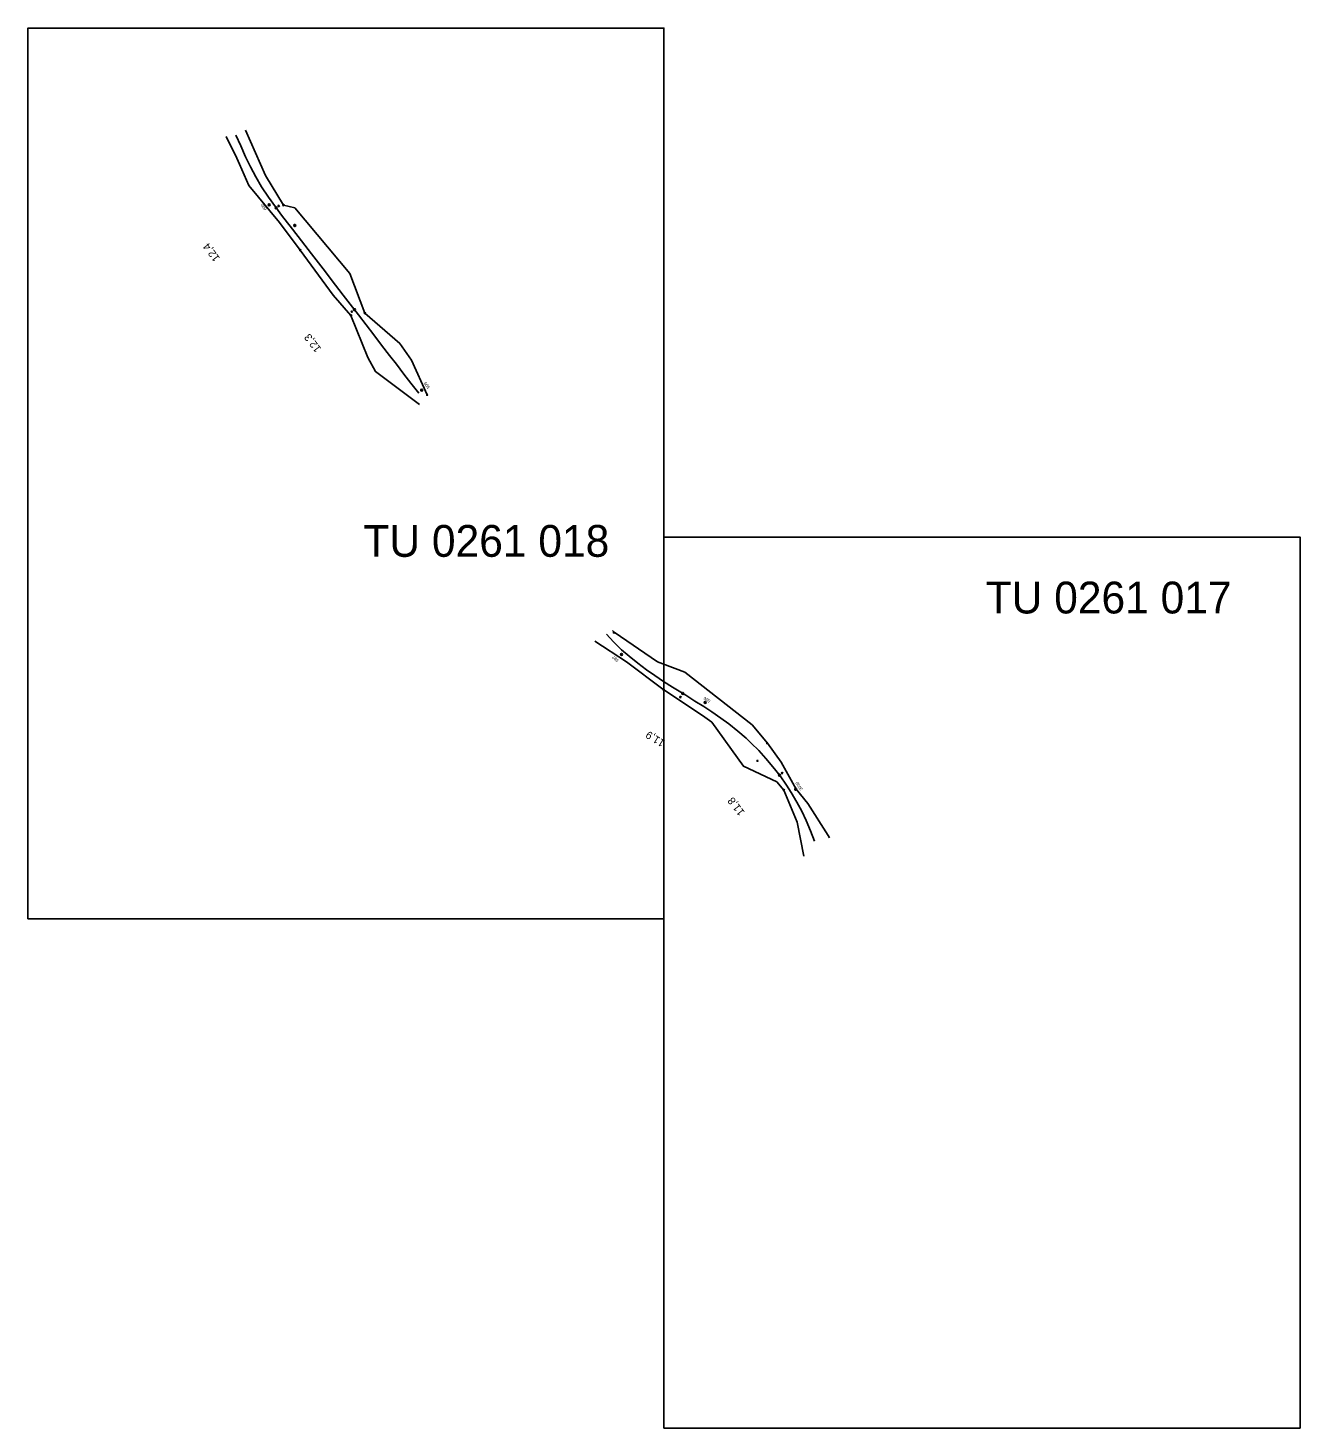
# Model space of a CAD drawing. Extents: x -849500 to -843400, y -1061500 to -1052696.
# Drawn here: x -849200 to -848200, y -1057300 to -1056200 of the extents above; entities that cross this region are included whole.
import ezdxf

# ---------------------------------------------------------------- set-up
doc = ezdxf.new("R2010")
doc.units = 0
for name, color, linetype in [('Level 1', 7, 'Continuous'), ('Level 2', 7, 'Continuous'), ('Vrstva 1', 7, 'Continuous'), ('Vrstva 53', 7, 'Continuous'), ('Vrstva 63', 7, 'Continuous'), ('Vrstva 7', 7, 'Continuous')]:
    doc.layers.add(name, color=color, linetype=linetype)

msp = doc.modelspace()

# ---------------------------------------------------------------- linework, layer by layer
at = {"layer": 'Level 1'}
for points in [[(-849200, -1056900), (-849200, -1056200), (-848700, -1056200), (-848700, -1056900), (-849200, -1056900)], [(-848700, -1057300), (-848700, -1056600), (-848200, -1056600), (-848200, -1057300), (-848700, -1057300)]]:
    msp.add_lwpolyline(points, dxfattribs=at)
at = {"layer": 'Vrstva 1'}
for points in [[(-848999.8, -1056348.1), (-849005.4, -1056340.6), (-849011, -1056332.8), (-849016.3, -1056324.7), (-849020.8, -1056317), (-849025, -1056309.1), (-849028.9, -1056301.1), (-849032.8, -1056292.6), (-849036.6, -1056284.2)], [(-848892.8, -1056486.9), (-848899, -1056479), (-848904.4, -1056471.9), (-848910.4, -1056464.2), (-848915.7, -1056457.3), (-848922, -1056449.1), (-848928.2, -1056441), (-848934.2, -1056433.2), (-848940.2, -1056425.4), (-848946.7, -1056417), (-848952.2, -1056409.8), (-848955.6, -1056405.5), (-848960.8, -1056398.7), (-848966.2, -1056391.7), (-848971.6, -1056384.6), (-848977.2, -1056377.4), (-848982.3, -1056370.7), (-848987.7, -1056363.8), (-848993.8, -1056355.8), (-848999.8, -1056348.1)], [(-848581.6, -1056838.8), (-848584.7, -1056830.7), (-848588.2, -1056822.7), (-848591.7, -1056815.3), (-848595.5, -1056808.2), (-848599.9, -1056800.8), (-848603.8, -1056794.8), (-848608.8, -1056787.6), (-848614.4, -1056780.4), (-848619.9, -1056773.9), (-848625.5, -1056767.8), (-848631.4, -1056761.9), (-848635.5, -1056758.1), (-848642, -1056752.5), (-848649.1, -1056746.8), (-848655.3, -1056742.3), (-848662.5, -1056737.4), (-848668.7, -1056733.2), (-848675.7, -1056728.8), (-848682.9, -1056724.3), (-848689.4, -1056720.3), (-848693.4, -1056717.8), (-848700.3, -1056713.4), (-848707.3, -1056708.8), (-848713.7, -1056704.3), (-848720.7, -1056699.1), (-848727.5, -1056693.6), (-848733.3, -1056688.5), (-848739.6, -1056682.4), (-848745.3, -1056676.4)]]:
    msp.add_lwpolyline(points, dxfattribs=at)
at = {"layer": 'Vrstva 53'}
for p, q in [((-848999.2, -1056339.1), (-848999.1, -1056339.1)), ((-848986.1, -1056374.5), (-848986, -1056374.5)), ((-848946.1, -1056425.8), (-848946, -1056425.8)), ((-848935.3, -1056424), (-848935.2, -1056424)), ((-848886.3, -1056488.2), (-848886.2, -1056488.2)), ((-848739.4, -1056675), (-848739.3, -1056675)), ((-848700.4, -1056719.9), (-848700.3, -1056719.9)), ((-848618.9, -1056761.9), (-848618.8, -1056761.9)), ((-848626.6, -1056775.8), (-848626.5, -1056775.8)), ((-848605.9, -1056798.8), (-848605.8, -1056798.8)), ((-848596.5, -1056798.1), (-848596.4, -1056798.1))]:
    msp.add_line(p, q, dxfattribs=at)
for points in [[(-849026.3, -1056323.7), (-849033.6, -1056307.1), (-849035.7, -1056302.4), (-849044.2, -1056285.3)], [(-849029, -1056280.3), (-849013.3, -1056316), (-848999.2, -1056339.1), (-848990.1, -1056341.4)], [(-848892.2, -1056495.7), (-848926.9, -1056470), (-848932.8, -1056458.9), (-848946.1, -1056425.9), (-848960.2, -1056409.9), (-848986, -1056374.6), (-849002.4, -1056352.8), (-849026.3, -1056323.7)], [(-848990.1, -1056341.4), (-848947, -1056392.8), (-848935.2, -1056424), (-848907.8, -1056448), (-848898.4, -1056460.9), (-848886.2, -1056488.2)], [(-849001.8, -1056353.5), (-849002.4, -1056352.8)], [(-848590.1, -1056850.6), (-848595.3, -1056823.9), (-848605.8, -1056798.8), (-848611.4, -1056792.4), (-848637.6, -1056780), (-848662.5, -1056745.3), (-848669.7, -1056740.3), (-848700.8, -1056719.4), (-848729.6, -1056697.9), (-848754.5, -1056681.9)], [(-848590.1, -1056850.6), (-848595.3, -1056823.9), (-848605.8, -1056798.8), (-848611.4, -1056792.4), (-848637.6, -1056780), (-848662.5, -1056745.3), (-848669.7, -1056740.3), (-848700.8, -1056719.4), (-848729.6, -1056697.9), (-848754.5, -1056681.9)], [(-848740.4, -1056673.5), (-848739.2, -1056674.8), (-848705.2, -1056698), (-848700.9, -1056699.6), (-848683.7, -1056706.1), (-848630.8, -1056747.4), (-848618.7, -1056761.9), (-848607.8, -1056776.9), (-848596.1, -1056798), (-848586.9, -1056809.4), (-848571, -1056834.4), (-848570, -1056836.3)], [(-848740.4, -1056673.5), (-848739.2, -1056674.8), (-848705.2, -1056698), (-848700.9, -1056699.6), (-848683.7, -1056706.1), (-848630.8, -1056747.4), (-848618.7, -1056761.9), (-848607.8, -1056776.9), (-848596.1, -1056798), (-848586.9, -1056809.4), (-848571, -1056834.4), (-848570, -1056836.3)]]:
    msp.add_lwpolyline(points, dxfattribs=at)
for centre in [(-848999.2, -1056339.1), (-848986, -1056374.5), (-848946.1, -1056425.8), (-848935.2, -1056424), (-848886.2, -1056488.2), (-848739.4, -1056675), (-848700.3, -1056719.9), (-848618.9, -1056761.9), (-848626.5, -1056775.8), (-848605.8, -1056798.8), (-848596.5, -1056798.1)]:
    msp.add_circle(centre, 0.499, dxfattribs=at)
at = {"layer": 'Vrstva 63'}
for p, q in [((-849010.5, -1056338.9), (-849010.4, -1056338.9)), ((-848990.3, -1056355.1), (-848991.1, -1056355)), ((-848991.1, -1056355), (-848989.5, -1056355.2)), ((-848990.3, -1056355.1), (-848991.1, -1056355)), ((-848991, -1056354.8), (-848990.3, -1056354.9)), ((-848990.8, -1056354.6), (-848990.2, -1056354.6)), ((-848990.2, -1056354.4), (-848990.4, -1056355.9)), ((-848990.3, -1056355.1), (-848990.4, -1056355.9)), ((-848990.4, -1056355.9), (-848990.3, -1056355.1)), ((-848990.4, -1056355.6), (-848989.8, -1056355.7)), ((-848990.2, -1056354.4), (-848990.3, -1056355.1)), ((-848990.3, -1056355.1), (-848989.5, -1056355.2)), ((-848990.3, -1056355.3), (-848989.6, -1056355.4)), ((-848890.5, -1056484.5), (-848890.4, -1056484.5)), ((-848733.4, -1056692.2), (-848733.3, -1056692.2)), ((-848667.6, -1056729.9), (-848667.5, -1056729.9)), ((-848596.5, -1056798.1), (-848596.4, -1056798.1))]:
    msp.add_line(p, q, dxfattribs=at)
for centre, radius in [((-849010.4, -1056338.9), 0.756), ((-848990.3, -1056355.1), 0.764), ((-848890.5, -1056484.5), 0.756), ((-848733.4, -1056692.2), 0.756), ((-848667.6, -1056729.9), 0.756), ((-848596.5, -1056798.1), 0.756)]:
    msp.add_circle(centre, radius, dxfattribs=at)
for radius, start, end in [(0.764, 82.1466, 172.4646), (0.765, 262.8354, 352.7289)]:
    msp.add_arc((-848990.3, -1056355.1), radius, start, end, dxfattribs=at)
at = {"layer": 'Vrstva 7'}
for p, q in [((-849002.9, -1056339.9), (-849003, -1056339.8)), ((-848945.4, -1056423), (-848945.5, -1056422.9)), ((-848687.1, -1056725.7), (-848687.2, -1056725.7)), ((-848607, -1056785.5), (-848607.1, -1056785.4))]:
    msp.add_line(p, q, dxfattribs=at)
for centre, radius in [((-849004.9, -1056341.3), 0.75), ((-849002.9, -1056339.8), 0.5), ((-848945.4, -1056422.9), 0.5), ((-848943.3, -1056421.3), 0.75), ((-848687.1, -1056725.7), 0.5), ((-848685.3, -1056722.8), 0.75), ((-848609.2, -1056787), 0.75), ((-848607.1, -1056785.4), 0.5)]:
    msp.add_circle(centre, radius, dxfattribs=at)

# ---------------------------------------------------------------- texts
at = {"layer": 'Level 2'}
for s, p in [('TU 0261 018', (-848936.3, -1056615.5)), ('TU 0261 017', (-848447.1, -1056660))]:
    msp.add_text(s, height=25, dxfattribs=at).set_placement(p)
at = {"layer": 'Vrstva 63'}
for s, rotation, p in [('600', 125.335, (-849012.1, -1056342.2)), ('599', 127.6996, (-848883.8, -1056482.2)), ('597', 138.4582, (-848735.3, -1056696.6)), ('596', 147.5497, (-848663.3, -1056728.2)), ('3030', 122.7592, (-848590.8, -1056798.1))]:
    msp.add_text(s, height=2.4, rotation=rotation, dxfattribs=at).set_placement(p)
at = {"layer": 'Vrstva 7'}
for s, rotation, p in [('12,4', 126.9838, (-849048.8, -1056380.8)), ('12,3', 127.5774, (-848969.1, -1056452)), ('11,9', 148.1054, (-848698.7, -1056760.3)), ('11,8', 127.7325, (-848636.2, -1056816.1))]:
    msp.add_text(s, height=6, rotation=rotation, dxfattribs=at).set_placement(p)

doc.saveas('drawing.dxf')
